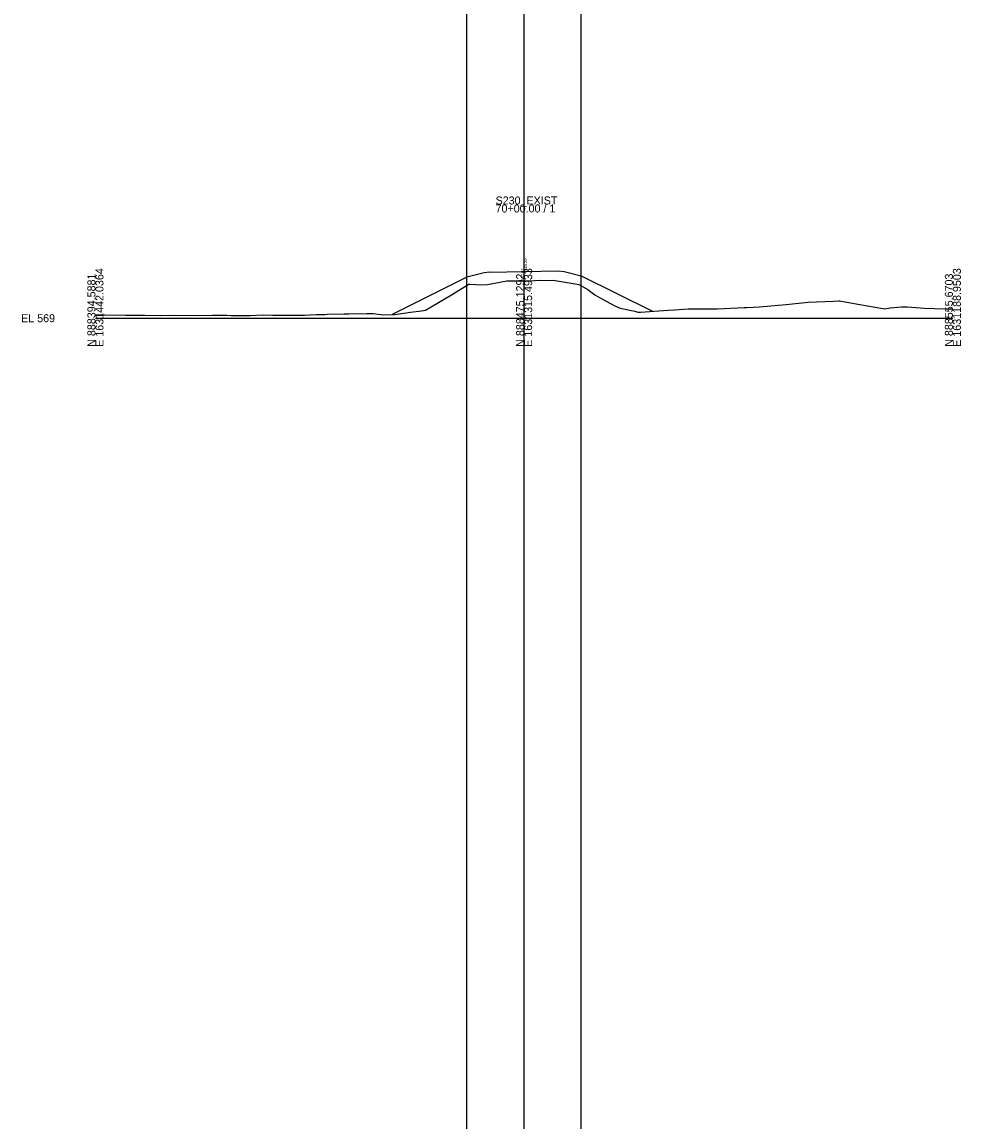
# Model space of a CAD drawing. Extents: x 1631115 to 1631443, y 885974 to 892071.
# Drawn here: x 1631114.8 to 1631443.3, y 888702.5 to 889087.2 of the extents above; entities that cross this region are included whole.
import ezdxf

# ---------------------------------------------------------------- set-up
doc = ezdxf.new("R2010")
doc.units = 0
for name, color, linetype in [('Default', 7, 'Continuous'), ('RD_GPK_XS_Cell', 7, 'Continuous'), ('RD_XS_EarthShd', 7, 'Continuous'), ('RD_XS_ExGround', 7, 'Continuous'), ('RD_XS_Pave', 7, 'Continuous'), ('RD_XS_TieSlope', 7, 'Continuous'), ('RD_XS_TX_Elev_EX', 7, 'Continuous'), ('RD_XS_TX_Elev_PR', 7, 'Continuous')]:
    doc.layers.add(name, color=color, linetype=linetype)

msp = doc.modelspace()

# ---------------------------------------------------------------- linework, layer by layer
at = {"layer": 'Default'}
for p, q in [((1631270.47, 885983.65), (1631270.47, 892068.63)), ((1631290.47, 885983.65), (1631290.47, 892068.63)), ((1631310.47, 885983.65), (1631310.47, 892068.63))]:
    msp.add_line(p, q, dxfattribs=at)
at = {"layer": 'RD_GPK_XS_Cell'}
for p, q in [((1631290.47, 888983.65), (1631290.47, 889023.43)), ((1631140.47, 888983.65), (1631290.47, 888983.65)), ((1631290.47, 888983.65), (1631440.47, 888983.65))]:
    msp.add_line(p, q, dxfattribs=at)
at = {"layer": 'RD_XS_EarthShd'}
for p, q in [((1631302.47, 889000.18), (1631304.47, 889000.02)), ((1631278.47, 888999.7), (1631276.47, 888999.54))]:
    msp.add_line(p, q, dxfattribs=at)
at = {"layer": 'RD_XS_ExGround'}
msp.add_lwpolyline([(1631140.47, 888984.81), (1631143.63, 888984.87), (1631151.16, 888984.76), (1631154.24, 888984.74), (1631157.65, 888984.76), (1631163.15, 888984.64), (1631168, 888984.68), (1631176.04, 888984.59), (1631181.45, 888984.66), (1631184.46, 888984.68), (1631186.46, 888984.66), (1631187.93, 888984.61), (1631189.23, 888984.57), (1631194.66, 888984.61), (1631199.21, 888984.86), (1631202.52, 888984.73), (1631204.37, 888984.73), (1631213.58, 888984.68), (1631215.65, 888984.83), (1631217.85, 888984.99), (1631220.69, 888984.95), (1631221.51, 888985.01), (1631227.48, 888985.16), (1631229.1, 888985.16), (1631235.47, 888985.27), (1631237.62, 888985.27), (1631241.24, 888984.85), (1631245.19, 888984.96), (1631250.65, 888985.75), (1631254.59, 888986.19), (1631255.97, 888986.48), (1631265.08, 888991.79), (1631266.91, 888993.04), (1631271.11, 888995.55), (1631271.44, 888995.58), (1631275.66, 888995.29), (1631277.59, 888995.41), (1631284.39, 888996.7), (1631285.41, 888996.7), (1631286.81, 888996.7), (1631288.02, 888996.68), (1631288.7, 888996.67), (1631290.47, 888996.72), (1631291.9, 888996.76), (1631294.07, 888996.84), (1631296.03, 888996.91), (1631299.28, 888996.89), (1631300.65, 888996.9), (1631308.3, 888995.71), (1631309.55, 888995.41), (1631310.02, 888995.22), (1631312.72, 888993.68), (1631315.24, 888991.87), (1631317.7, 888990.46), (1631322.2, 888987.93), (1631324.1, 888987.15), (1631329.18, 888986.07), (1631330.29, 888985.81), (1631330.67, 888985.78), (1631331.22, 888985.81), (1631340.8, 888986.43), (1631343.11, 888986.6), (1631347.8, 888986.94), (1631351.52, 888986.96), (1631358.15, 888986.97), (1631367.45, 888987.34), (1631367.77, 888987.35), (1631368.35, 888987.37), (1631372.79, 888987.61), (1631376.73, 888988), (1631382.16, 888988.44), (1631389.79, 888989.27), (1631398.73, 888989.63), (1631400.44, 888989.71), (1631400.75, 888989.72), (1631407.89, 888988.45), (1631415.98, 888987.1), (1631416.61, 888986.9), (1631418.57, 888987.27), (1631422.51, 888987.64), (1631424.46, 888987.61), (1631430.54, 888987.12), (1631437.81, 888986.89), (1631440.47, 888986.92)], dxfattribs=at)
at = {"layer": 'RD_XS_Pave'}
for p, q in [((1631278.47, 888999.7), (1631290.47, 888999.94)), ((1631290.47, 888999.94), (1631302.47, 889000.18))]:
    msp.add_line(p, q, dxfattribs=at)
at = {"layer": 'RD_XS_TieSlope'}
for p, q in [((1631304.47, 889000.02), (1631310.47, 888998.52)), ((1631270.47, 888998.04), (1631244.25, 888984.93)), ((1631276.47, 888999.54), (1631270.47, 888998.04)), ((1631310.47, 888998.52), (1631335.37, 888986.08))]:
    msp.add_line(p, q, dxfattribs=at)

# ---------------------------------------------------------------- texts
at = {"layer": 'RD_GPK_XS_Cell'}
for s, p in [('S230_EXIST', (1631280.47, 889023.43)), ('70+00.00 / 1', (1631280.47, 889020.63)), ('EL 569', (1631114.47, 888982.25))]:
    msp.add_text(s, height=2.8, dxfattribs=at).set_placement(p)
for s, p in [('E 1631442.0364', (1631143.27, 888973.65)), ('E 1631315.4933', (1631293.27, 888973.65)), ('E 1631188.9503', (1631443.27, 888973.65)), ('N 888394.5881', (1631140.47, 888973.65)), ('N 888475.1292', (1631290.47, 888973.65)), ('N 888555.6703', (1631440.47, 888973.65))]:
    msp.add_text(s, height=2.8, rotation=90, dxfattribs=at).set_placement(p)
at = {"layer": 'RD_XS_TX_Elev_EX'}
msp.add_text('582.07', height=1, rotation=90, dxfattribs=at).set_placement((1631290.37, 888996.82))
at = {"layer": 'RD_XS_TX_Elev_PR'}
msp.add_text(' 585.29', height=1, rotation=90, dxfattribs=at).set_placement((1631291.47, 888999.94))

doc.saveas('drawing.dxf')
